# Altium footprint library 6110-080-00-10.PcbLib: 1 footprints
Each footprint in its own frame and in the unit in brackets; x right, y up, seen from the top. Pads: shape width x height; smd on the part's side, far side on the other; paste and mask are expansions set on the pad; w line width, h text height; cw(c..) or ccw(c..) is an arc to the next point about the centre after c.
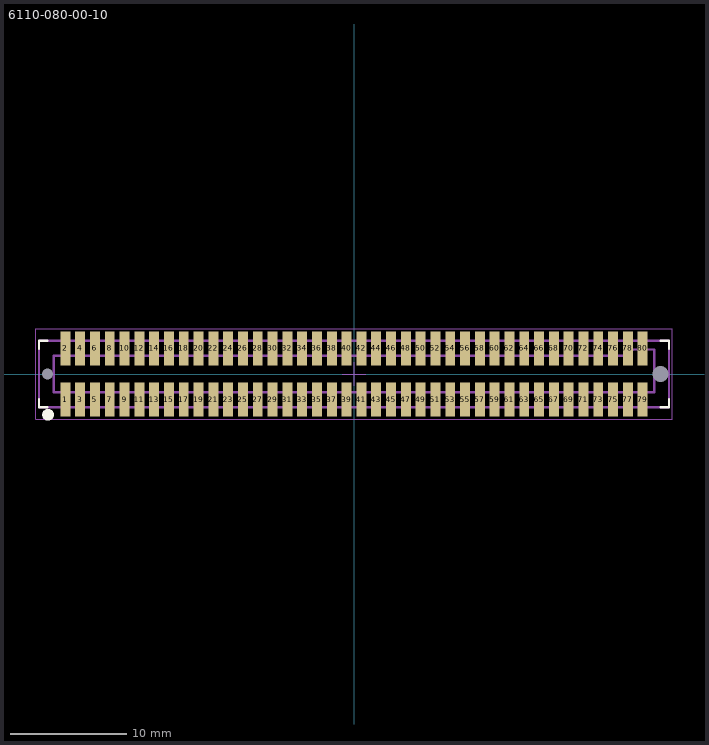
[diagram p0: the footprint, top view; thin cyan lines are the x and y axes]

## 6110-080-00-10 [mm]
height 5.61
pads (82):
  rect 0.85x2.9 smd: 1(-24.765,-2.2) 2(-24.765,2.2) 3(-23.495,-2.2) 4(-23.495,2.2) 5(-22.225,-2.2) 6(-22.225,2.2) 7(-20.955,-2.2) 8(-20.955,2.2) 9(-19.685,-2.2) 10(-19.685,2.2) 11(-18.415,-2.2) 12(-18.415,2.2) 13(-17.145,-2.2) 14(-17.145,2.2) 15(-15.875,-2.2) 16(-15.875,2.2) 17(-14.605,-2.2) 18(-14.605,2.2) 19(-13.335,-2.2) 20(-13.335,2.2) 21(-12.065,-2.2) 22(-12.065,2.2) 23(-10.795,-2.2) 24(-10.795,2.2) 25(-9.525,-2.2) 26(-9.525,2.2) 27(-8.255,-2.2) 28(-8.255,2.2) 29(-6.985,-2.2) 30(-6.985,2.2) 31(-5.715,-2.2) 32(-5.715,2.2) 33(-4.445,-2.2) 34(-4.445,2.2) 35(-3.175,-2.2) 36(-3.175,2.2) 37(-1.905,-2.2) 38(-1.905,2.2) 39(-0.635,-2.2) 40(-0.635,2.2) 41(0.635,-2.2) 42(0.635,2.2) 43(1.905,-2.2) 44(1.905,2.2) 45(3.175,-2.2) 46(3.175,2.2) 47(4.445,-2.2) 48(4.445,2.2) 49(5.715,-2.2) 50(5.715,2.2) 51(6.985,-2.2) 52(6.985,2.2) 53(8.255,-2.2) 54(8.255,2.2) 55(9.525,-2.2) 56(9.525,2.2) 57(10.795,-2.2) 58(10.795,2.2) 59(12.065,-2.2) 60(12.065,2.2) 61(13.335,-2.2) 62(13.335,2.2) 63(14.605,-2.2) 64(14.605,2.2) 65(15.875,-2.2) 66(15.875,2.2) 67(17.145,-2.2) 68(17.145,2.2) 69(18.415,-2.2) 70(18.415,2.2) 71(19.685,-2.2) 72(19.685,2.2) 73(20.955,-2.2) 74(20.955,2.2) 75(22.225,-2.2) 76(22.225,2.2) 77(23.495,-2.2) 78(23.495,2.2) 79(24.765,-2.2) 80(24.765,2.2)
  round 0 hole 0.95 unplated: H1(-26.29,0)
  round 0 hole 1.35 unplated: H2(26.29,0)
Top Overlay:
  circle w0.5: c-26.25,-3.5 r0.25
  lines w0.2: -27.03,-2.155 -27.03,-2.855 -26.33,-2.855 ; -27.03,2.155 -27.03,2.855 -26.33,2.855 ; 26.33,-2.855 27.03,-2.855 27.03,-2.155 ; 26.33,2.855 27.03,2.855 27.03,2.155
Assembly Top:
  lines w0.2: -27.03,-2.855 -27.03,2.855 27.03,2.855 27.03,-2.855 -27.03,-2.855 ; -25.755,-1.575 -25.755,1.575 23.35,1.575 23.95,2.1 25.755,2.1 25.755,1.575 25.755,-1.575 -25.755,-1.575
  text ".Designator" at -2,-0.5 h1
  text "79" at 23.8,-1.2 h1
  text "80" at 23.8,0.2 h1
  text "1" at -24.9,-1.2 h1
  text "2" at -25.1,0.2 h1
Courtyard Top:
  lines w0.05: -1,0 1,0 ; 0,-1 0,1 ; -27.3,-3.9 27.3,-3.9 27.3,3.9 -27.3,3.9 -27.3,-3.9
3D body: height 5.61, standoff 0, extent -27.03,-2.855 27.03,2.855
